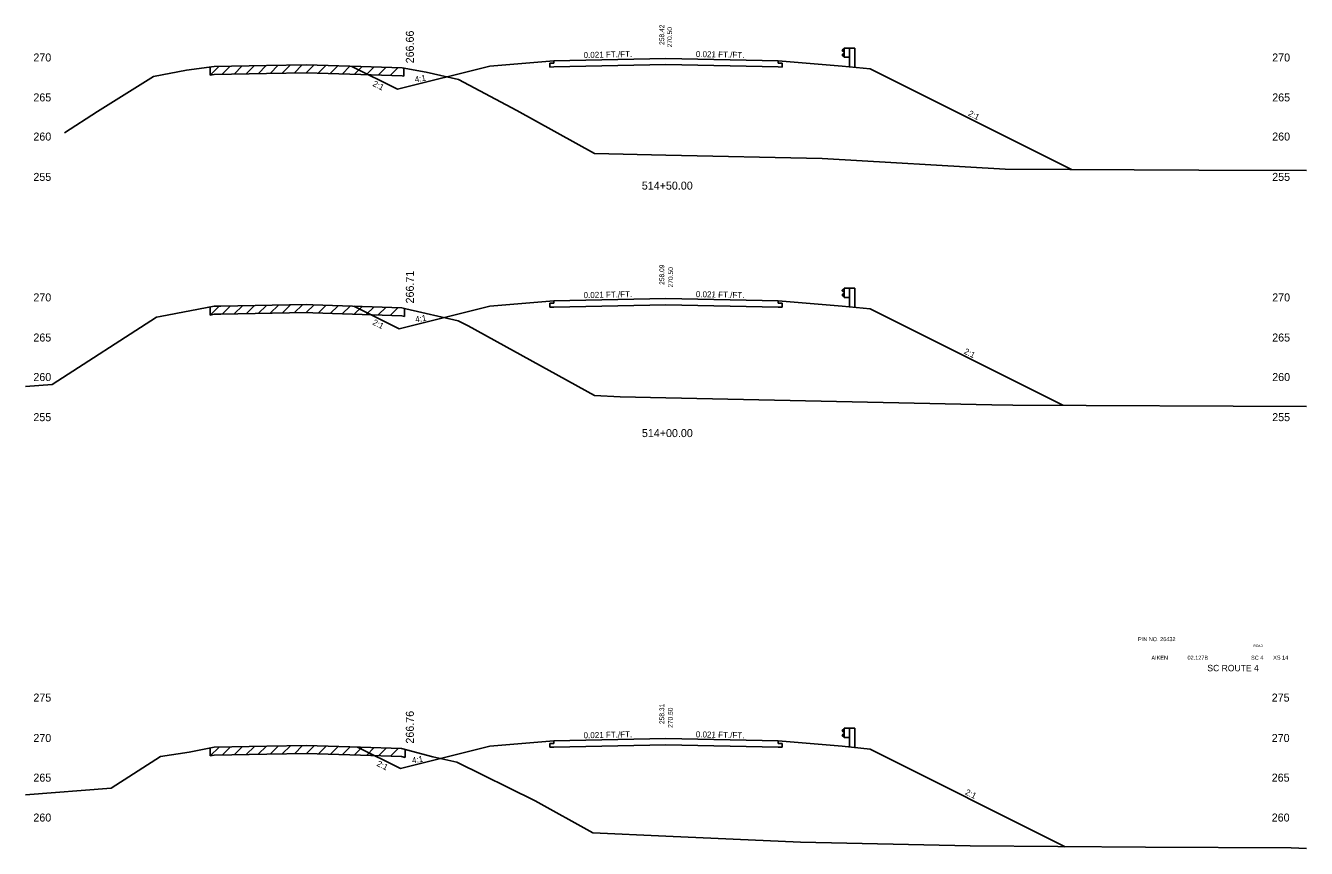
# Model space of a CAD drawing. Extents: x 883 to 1160, y 1002 to 4323.
# Drawn here: x 1000 to 1160, y 2571.8 to 2674.6 of the extents above; entities that cross this region are included whole.
import ezdxf

# ---------------------------------------------------------------- set-up
doc = ezdxf.new("R2010")
doc.units = 0
for name, color, linetype in [('Level 1', 7, 'Continuous'), ('Level 10', 7, 'Continuous'), ('Level 11', 7, 'Continuous'), ('Level 12', 7, 'Continuous'), ('Level 24', 7, 'Continuous'), ('Level 3', 7, 'Continuous'), ('Level 32', 7, 'Continuous'), ('Level 33', 7, 'Continuous'), ('Level 59', 7, 'Continuous'), ('Level 6', 7, 'Continuous'), ('Level 60', 7, 'Continuous'), ('Level 61', 7, 'Continuous'), ('Level 7', 7, 'Continuous')]:
    doc.layers.add(name, color=color, linetype=linetype)

msp = doc.modelspace()

# ---------------------------------------------------------------- linework, layer by layer
at = {"layer": 'Level 11'}
for p, q in [((1066, 2669.91), (1065.5, 2669.9)), ((1065.5, 2669.9), (1065.5, 2669.42)), ((1065.5, 2669.42), (1066, 2669.43)), ((1066, 2670.21), (1066, 2669.91)), ((1094, 2669.91), (1094, 2670.21)), ((1094.5, 2669.9), (1094, 2669.91)), ((1094, 2669.43), (1094.5, 2669.42)), ((1094.5, 2669.42), (1094.5, 2669.9)), ((1066, 2640.21), (1066, 2639.91)), ((1094, 2639.91), (1094, 2640.21)), ((1066, 2639.91), (1065.5, 2639.9)), ((1065.5, 2639.9), (1065.5, 2639.42)), ((1065.5, 2639.42), (1066, 2639.43)), ((1094.5, 2639.9), (1094, 2639.91)), ((1094, 2639.43), (1094.5, 2639.42)), ((1094.5, 2639.42), (1094.5, 2639.9)), ((1066, 2584.91), (1065.5, 2584.9)), ((1065.5, 2584.9), (1065.5, 2584.42)), ((1065.5, 2584.42), (1066, 2584.43)), ((1066, 2585.21), (1066, 2584.91)), ((1094, 2584.91), (1094, 2585.21)), ((1094.5, 2584.9), (1094, 2584.91)), ((1094, 2584.43), (1094.5, 2584.42)), ((1094.5, 2584.42), (1094.5, 2584.9))]:
    msp.add_line(p, q, dxfattribs=at)
at = {"layer": 'Level 12'}
for p, q in [((1080, 2669.72), (1066, 2669.43)), ((1094, 2669.43), (1080, 2669.72)), ((1080, 2639.72), (1066, 2639.43)), ((1094, 2639.43), (1080, 2639.72)), ((1080, 2584.72), (1066, 2584.43)), ((1094, 2584.43), (1080, 2584.72))]:
    msp.add_line(p, q, dxfattribs=at)
at = {"layer": 'Level 24'}
for p, q in [((1102.27, 2671.72), (1102, 2671.52)), ((1102, 2671.52), (1102, 2671.47)), ((1102, 2671.47), (1102.27, 2671.27)), ((1102, 2670.95), (1102.27, 2671.15)), ((1102, 2670.9), (1102, 2670.95)), ((1102.27, 2670.7), (1102, 2670.9)), ((1102.27, 2670.63), (1102.27, 2671.79)), ((1102.27, 2671.79), (1102.94, 2671.79)), ((1102.27, 2670.63), (1102.94, 2670.63)), ((1102.94, 2671.79), (1102.94, 2669.45)), ((1102.94, 2671.79), (1103.6, 2671.79)), ((1103.6, 2671.79), (1103.6, 2669.38)), ((1102.27, 2641.72), (1102, 2641.52)), ((1102.27, 2640.63), (1102.27, 2641.79)), ((1102.27, 2641.79), (1102.94, 2641.79)), ((1102.94, 2641.79), (1102.94, 2639.45)), ((1102.94, 2641.79), (1103.6, 2641.79)), ((1103.6, 2641.79), (1103.6, 2639.38)), ((1102, 2641.52), (1102, 2641.47)), ((1102, 2641.47), (1102.27, 2641.27)), ((1102, 2640.95), (1102.27, 2641.15)), ((1102, 2640.9), (1102, 2640.95)), ((1102.27, 2640.7), (1102, 2640.9)), ((1102.27, 2640.63), (1102.94, 2640.63)), ((1102.27, 2586.72), (1102, 2586.52)), ((1102, 2586.52), (1102, 2586.47)), ((1102, 2586.47), (1102.27, 2586.27)), ((1102, 2585.95), (1102.27, 2586.15)), ((1102, 2585.9), (1102, 2585.95)), ((1102.27, 2585.7), (1102, 2585.9)), ((1102.27, 2585.63), (1102.27, 2586.79)), ((1102.27, 2586.79), (1102.94, 2586.79)), ((1102.27, 2585.63), (1102.94, 2585.63)), ((1102.94, 2586.79), (1102.94, 2584.45)), ((1102.94, 2586.79), (1103.6, 2586.79)), ((1103.6, 2586.79), (1103.6, 2584.38))]:
    msp.add_line(p, q, dxfattribs=at)
at = {"layer": 'Level 59'}
for p, q in [((1066, 2670.21), (1080, 2670.5)), ((1080, 2670.5), (1094, 2670.21)), ((1066, 2640.21), (1080, 2640.5)), ((1080, 2640.5), (1094, 2640.21)), ((1066, 2585.21), (1080, 2585.5)), ((1080, 2585.5), (1094, 2585.21))]:
    msp.add_line(p, q, dxfattribs=at)
at = {"layer": 'Level 6'}
for p, q in [((1058, 2669.54), (1066, 2670.21)), ((1094, 2670.21), (1102, 2669.54)), ((1102, 2669.54), (1105.5, 2669.19)), ((1058, 2639.54), (1066, 2640.21)), ((1094, 2640.21), (1102, 2639.54)), ((1102, 2639.54), (1105.5, 2639.19)), ((1058, 2584.54), (1066, 2585.21)), ((1094, 2585.21), (1102, 2584.54)), ((1102, 2584.54), (1105.5, 2584.19))]:
    msp.add_line(p, q, dxfattribs=at)
at = {"layer": 'Level 60'}
for p, q in [((1015.97, 2668.23), (1020.09, 2669.02)), ((1020.09, 2669.02), (1023.54, 2669.49)), ((1023.54, 2669.49), (1030.09, 2669.6)), ((1030.09, 2669.6), (1035.05, 2669.69)), ((1035.05, 2669.69), (1041.88, 2669.47)), ((1041.88, 2669.47), (1047.05, 2669.31)), ((1047.05, 2669.31), (1050.04, 2668.79)), ((1008.99, 2663.87), (1015.97, 2668.23)), ((1050.04, 2668.79), (1054.08, 2667.85)), ((1054.08, 2667.85), (1061.38, 2663.98)), ((1004.85, 2661.21), (1008.99, 2663.87)), ((1061.38, 2663.98), (1071.07, 2658.62)), ((1071.07, 2658.62), (1080, 2658.42)), ((1080, 2658.42), (1099.5, 2658)), ((1099.5, 2658), (1122.38, 2656.65)), ((1122.38, 2656.65), (1146.55, 2656.54)), ((1146.55, 2656.54), (1160, 2656.5)), ((1016.8, 2638.23), (1023.55, 2639.53)), ((1023.55, 2639.53), (1024.37, 2639.54)), ((1024.37, 2639.54), (1035.07, 2639.73)), ((1035.07, 2639.73), (1035.89, 2639.7)), ((1035.89, 2639.7), (1047.01, 2639.34)), ((1047.01, 2639.34), (1047.5, 2639.21)), ((1047.5, 2639.21), (1054.05, 2637.69)), ((1003.31, 2629.77), (1016.36, 2638.16)), ((1016.36, 2638.16), (1016.8, 2638.23)), ((1054.05, 2637.69), (1055.28, 2637.08)), ((1055.28, 2637.08), (1071.05, 2628.36)), ((1000, 2629.52), (1003.31, 2629.77)), ((1071.05, 2628.36), (1074.27, 2628.22)), ((1074.27, 2628.22), (1080, 2628.09)), ((1080, 2628.09), (1120.7, 2627.2)), ((1120.7, 2627.2), (1123.34, 2627.18)), ((1123.34, 2627.18), (1160, 2627.01)), ((1020.44, 2583.83), (1023.56, 2584.43)), ((1023.56, 2584.43), (1030.15, 2584.56)), ((1030.15, 2584.56), (1035.09, 2584.65)), ((1035.09, 2584.65), (1041.83, 2584.44)), ((1041.83, 2584.44), (1046.96, 2584.27)), ((1046.96, 2584.27), (1050.87, 2583.24)), ((1010.7, 2579.31), (1016.84, 2583.25)), ((1016.84, 2583.25), (1020.44, 2583.83)), ((1050.87, 2583.24), (1053.88, 2582.54)), ((1053.88, 2582.54), (1063.64, 2577.72)), ((1000, 2578.48), (1010.7, 2579.31)), ((1063.64, 2577.72), (1070.88, 2573.71)), ((1070.88, 2573.71), (1080, 2573.31)), ((1080, 2573.31), (1096.8, 2572.56)), ((1096.8, 2572.56), (1118, 2572.1)), ((1118, 2572.1), (1139.92, 2571.92)), ((1139.92, 2571.92), (1158.11, 2571.84)), ((1158.11, 2571.84), (1160, 2571.79))]:
    msp.add_line(p, q, dxfattribs=at)
at = {"layer": 'Level 61'}
for p, q in [((1024.12, 2669.5), (1023.05, 2668.42)), ((1023.05, 2669.42), (1023.05, 2668.42)), ((1025.56, 2669.52), (1024.55, 2668.51)), ((1027.06, 2669.55), (1026.05, 2668.53)), ((1028.56, 2669.58), (1027.55, 2668.56)), ((1030.06, 2669.6), (1029.05, 2668.58)), ((1031.56, 2669.63), (1030.55, 2668.61)), ((1033.06, 2669.65), (1032.05, 2668.64)), ((1034.56, 2669.68), (1033.55, 2668.66)), ((1036.01, 2669.66), (1035.05, 2668.69)), ((1037.51, 2669.61), (1036.55, 2668.64)), ((1039.01, 2669.56), (1038.05, 2668.59)), ((1040.51, 2669.51), (1039.55, 2668.54)), ((1042.01, 2669.46), (1041.05, 2668.49)), ((1043.52, 2669.42), (1042.55, 2668.45)), ((1045.02, 2669.37), (1044.05, 2668.4)), ((1046.52, 2669.32), (1045.55, 2668.35)), ((1047.25, 2668.27), (1047.25, 2669.27)), ((1023.05, 2668.42), (1023.54, 2668.49)), ((1023.54, 2668.49), (1030.09, 2668.6)), ((1030.09, 2668.6), (1035.05, 2668.69)), ((1035.05, 2668.69), (1041.88, 2668.47)), ((1041.88, 2668.47), (1047.05, 2668.31)), ((1047.05, 2668.31), (1047.25, 2668.27)), ((1024.16, 2639.54), (1023.06, 2638.43)), ((1023.06, 2639.43), (1023.06, 2638.43)), ((1023.06, 2638.43), (1023.55, 2638.53)), ((1023.55, 2638.53), (1024.37, 2638.54)), ((1024.37, 2638.54), (1035.07, 2638.73)), ((1025.58, 2639.56), (1024.56, 2638.55)), ((1027.08, 2639.59), (1026.06, 2638.57)), ((1028.58, 2639.62), (1027.56, 2638.6)), ((1030.08, 2639.64), (1029.06, 2638.62)), ((1031.58, 2639.67), (1030.56, 2638.65)), ((1033.08, 2639.69), (1032.06, 2638.68)), ((1034.58, 2639.72), (1033.56, 2638.7)), ((1036.03, 2639.7), (1035.06, 2638.73)), ((1035.07, 2638.73), (1035.89, 2638.7)), ((1035.89, 2638.7), (1047.01, 2638.34)), ((1037.53, 2639.65), (1036.56, 2638.68)), ((1039.03, 2639.6), (1038.06, 2638.63)), ((1040.53, 2639.55), (1039.56, 2638.58)), ((1042.03, 2639.5), (1041.06, 2638.53)), ((1043.53, 2639.45), (1042.56, 2638.49)), ((1045.03, 2639.4), (1044.06, 2638.44)), ((1046.53, 2639.36), (1045.56, 2638.39)), ((1047.33, 2638.26), (1047.33, 2639.26)), ((1047.01, 2638.34), (1047.33, 2638.26)), ((1024.18, 2584.44), (1023.07, 2583.34)), ((1023.07, 2584.34), (1023.07, 2583.34)), ((1025.59, 2584.47), (1024.57, 2583.45)), ((1027.09, 2584.5), (1026.07, 2583.48)), ((1028.59, 2584.53), (1027.57, 2583.51)), ((1030.09, 2584.56), (1029.07, 2583.54)), ((1031.59, 2584.59), (1030.57, 2583.57)), ((1033.09, 2584.61), (1032.07, 2583.6)), ((1034.59, 2584.64), (1033.57, 2583.62)), ((1036.04, 2584.62), (1035.07, 2583.65)), ((1037.54, 2584.57), (1036.57, 2583.6)), ((1039.04, 2584.52), (1038.07, 2583.56)), ((1040.54, 2584.48), (1039.57, 2583.51)), ((1042.04, 2584.43), (1041.07, 2583.46)), ((1043.54, 2584.38), (1042.57, 2583.41)), ((1045.04, 2584.33), (1044.07, 2583.36)), ((1046.54, 2584.28), (1045.57, 2583.32)), ((1047.41, 2583.15), (1047.41, 2584.15)), ((1023.07, 2583.34), (1023.56, 2583.43)), ((1023.56, 2583.43), (1030.15, 2583.56)), ((1030.15, 2583.56), (1035.09, 2583.65)), ((1035.09, 2583.65), (1041.83, 2583.44)), ((1041.83, 2583.44), (1046.96, 2583.27)), ((1046.96, 2583.27), (1047.41, 2583.15))]:
    msp.add_line(p, q, dxfattribs=at)
at = {"layer": 'Level 7'}
for p, q in [((1040.76, 2669.5), (1046.45, 2666.66)), ((1058, 2669.54), (1046.45, 2666.66)), ((1105.5, 2669.19), (1130.66, 2656.61)), ((1040.99, 2639.54), (1046.65, 2636.71)), ((1058, 2639.54), (1046.65, 2636.71)), ((1105.5, 2639.19), (1129.59, 2627.15)), ((1041.47, 2584.45), (1046.85, 2581.76)), ((1058, 2584.54), (1046.85, 2581.76)), ((1105.5, 2584.19), (1129.88, 2572))]:
    msp.add_line(p, q, dxfattribs=at)

# ---------------------------------------------------------------- texts
at = {"layer": 'Level 1'}
for s, height, p in [('514+50.00', 1, (1076.98, 2654.1)), ('514+00.00', 1, (1076.99, 2623.18)), ('PIN NO. 26432', 0.5, (1138.97, 2597.68)), ('AIKEN', 0.5, (1140.64, 2595.36)), ('02.127B', 0.5, (1145.15, 2595.36)), ('SC 4', 0.5, (1153.09, 2595.36)), ('XS 14', 0.5, (1155.85, 2595.38)), ('SC ROUTE 4', 0.8, (1147.63, 2593.92))]:
    msp.add_text(s, height=height, dxfattribs=at).set_placement(p)
at = {"layer": 'Level 10'}
for s, p in [('258.42', (1079.78, 2672.18)), ('258.09', (1079.78, 2642.2)), ('258.31', (1079.78, 2587.32))]:
    msp.add_text(s, height=0.6, rotation=90, dxfattribs=at).set_placement(p)
at = {"layer": 'Level 3'}
for s, height, p in [(' 270', 1, (1000.6, 2670.11)), (' 270', 1, (1155.36, 2670.11)), (' 265', 1, (1000.6, 2665.12)), (' 265', 1, (1155.36, 2665.12)), (' 260', 1, (1000.6, 2660.23)), (' 260', 1, (1155.36, 2660.23)), (' 255', 1, (1000.6, 2655.19)), (' 255', 1, (1155.36, 2655.19)), (' 270', 1, (1000.6, 2640.13)), (' 270', 1, (1155.36, 2640.13)), (' 265', 1, (1000.6, 2635.12)), (' 265', 1, (1155.36, 2635.12)), (' 260', 1, (1000.6, 2630.18)), (' 260', 1, (1155.36, 2630.18)), (' 255', 1, (1000.6, 2625.17)), (' 255', 1, (1155.36, 2625.17)), ('ROAD', 0.3, (1153.38, 2596.95)), (' 275', 1, (1000.6, 2590.13)), (' 275', 1, (1155.3, 2590.13)), (' 270', 1, (1000.6, 2585.08)), (' 270', 1, (1155.3, 2585.08)), (' 265', 1, (1000.6, 2580.13)), (' 265', 1, (1155.3, 2580.13)), (' 260', 1, (1000.6, 2575.14)), (' 260', 1, (1155.3, 2575.14))]:
    msp.add_text(s, height=height, dxfattribs=at).set_placement(p)
at = {"layer": 'Level 32'}
for s, rotation, p in [('0.021 FT./FT.', 1.1916, (1069.71, 2670.54)), ('0.021 FT./FT.', 358.8084, (1083.72, 2670.67)), ('2:1', 333.435, (1043.28, 2667.09)), ('4:1', 9.4623, (1048.68, 2667.5)), ('2:1', 333.435, (1117.68, 2663.38)), ('0.021 FT./FT.', 1.1916, (1069.71, 2640.54)), ('0.021 FT./FT.', 358.8084, (1083.72, 2640.67)), ('4:1', 9.4623, (1048.74, 2637.5)), ('2:1', 333.435, (1043.27, 2637.27)), ('2:1', 333.435, (1117.15, 2633.65)), ('0.021 FT./FT.', 1.1916, (1069.71, 2585.54)), ('0.021 FT./FT.', 358.8084, (1083.72, 2585.67)), ('2:1', 333.435, (1043.79, 2582.14)), ('4:1', 9.4623, (1048.33, 2582.4)), ('2:1', 333.435, (1117.3, 2578.57))]:
    msp.add_text(s, height=0.75, rotation=rotation, dxfattribs=at).set_placement(p)
at = {"layer": 'Level 33'}
for s, p in [('266.66', (1048.5, 2669.88)), ('266.71', (1048.5, 2639.88)), ('266.76', (1048.5, 2584.88))]:
    msp.add_text(s, height=1, rotation=90, dxfattribs=at).set_placement(p)
at = {"layer": 'Level 59'}
for p in [(1080.76, 2671.65), (1080.88, 2641.65), (1080.85, 2586.62)]:
    msp.add_text(' 270.50', height=0.6, rotation=90, dxfattribs=at).set_placement(p)

doc.saveas('drawing.dxf')
